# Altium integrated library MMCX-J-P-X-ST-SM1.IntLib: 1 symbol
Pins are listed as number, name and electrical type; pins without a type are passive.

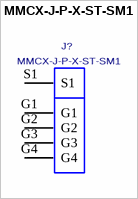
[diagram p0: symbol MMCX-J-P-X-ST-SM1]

## MMCX-J-P-X-ST-SM1
designator J?
MMCX STRAIGHT, SMT JACK- 50 OHM.; MANUFACTURER: SAMTEC
footprint MMCX-J-P-X-ST-SM1
pins: G1, G2, G3, G4, S1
